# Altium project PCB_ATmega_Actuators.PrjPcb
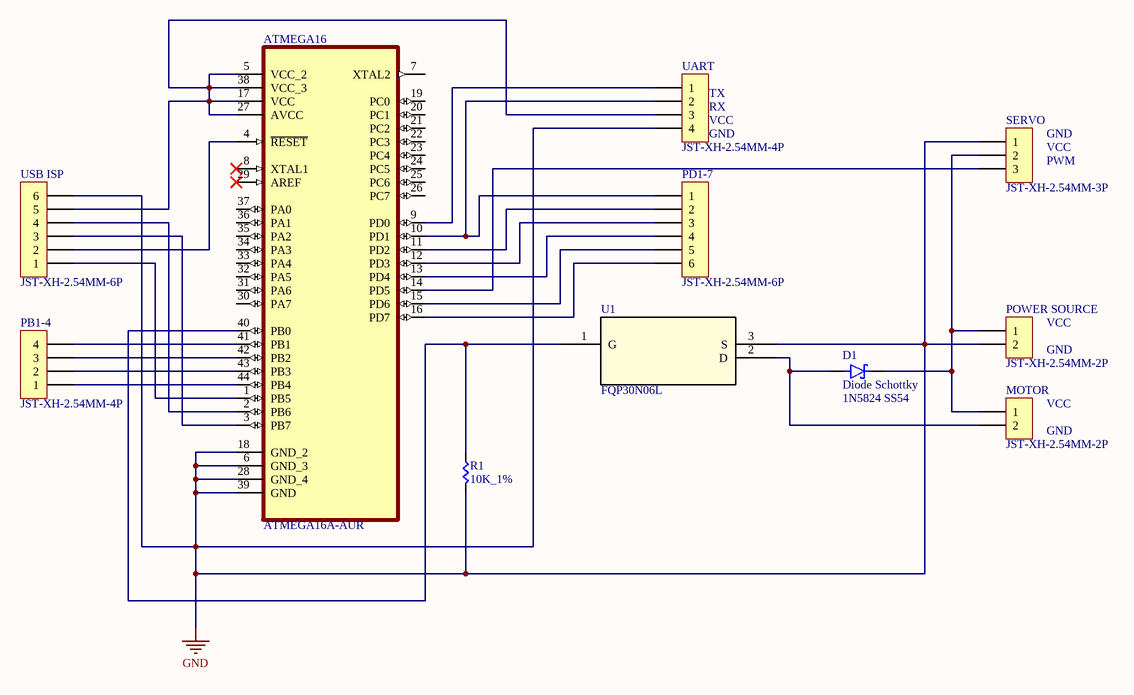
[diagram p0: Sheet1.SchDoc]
1 sheet, 11 parts. Net scope: global (net labels, ports and power ports of the same name join across sheets).
Board file: PCB1.PcbDoc

## Sheet Sheet1.SchDoc
size A3; SheetNumber: 1; SheetTotal: 1

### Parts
ATMEGA16  ATMEGA16A-AUR  [ATmega16_SMD]
D1  Diode Schottky  [1N5824 SS54]
MOTOR  Name: JST-XH-2.54MM-2P  [JST XH 2P-H 2.54mm]  (hidden comment: CN_JST_XH_2P_2.54MM)
PB1-4  Name: JST-XH-2.54MM-4P  [JST XH 4P-H 2.54mm]  (hidden comment: CN_JST_XH_4P_2.54MM)
PD1-7  Name: JST-XH-2.54MM-6P  [JST XH 6P-H 2.54mm]  (hidden comment: CN_JST_XH_6P_2.54MM)
POWER_SOURCE  Name: JST-XH-2.54MM-2P  [JST XH 2P-H 2.54mm]  (hidden comment: CN_JST_XH_2P_2.54MM)
R1  10K_1%  [RES 0805_2012]
SERVO  Name: JST-XH-2.54MM-3P  [JST XH 3P-H 2.54mm]  (hidden comment: CN_JST_XH_3P_2.54MM)
U1  FQP30N06L  [TO-220]
UART  Name: JST-XH-2.54MM-4P  [JST XH 4P-H 2.54mm]  (hidden comment: CN_JST_XH_4P_2.54MM)
USB_ISP  Name: JST-XH-2.54MM-6P  [JST XH 6P-H 2.54mm]  (hidden comment: CN_JST_XH_6P_2.54MM)

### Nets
GND: ATMEGA16.6(GND_3) ATMEGA16.18(GND_2) ATMEGA16.28(GND_4) ATMEGA16.39(GND) POWER_SOURCE.2 R1.2 SERVO.1 U1.3(S) UART.4 USB_ISP.6
NetATMEGA16_1: ATMEGA16.1(PB5) USB_ISP.1
NetATMEGA16_2: ATMEGA16.2(PB6) USB_ISP.4
NetATMEGA16_3: ATMEGA16.3(PB7) USB_ISP.3
NetATMEGA16_4: ATMEGA16.4(~{RESET}) USB_ISP.2
NetATMEGA16_5: ATMEGA16.5(VCC_2) ATMEGA16.17(VCC) ATMEGA16.27(AVCC) ATMEGA16.38(VCC_3) UART.3 USB_ISP.5
NetATMEGA16_9: ATMEGA16.9(PD0) UART.1
NetATMEGA16_10: ATMEGA16.10(PD1) PD1-7.1 UART.2
NetATMEGA16_11: ATMEGA16.11(PD2) PD1-7.2
NetATMEGA16_12: ATMEGA16.12(PD3) PD1-7.3
NetATMEGA16_13: ATMEGA16.13(PD4) PD1-7.4
NetATMEGA16_14: ATMEGA16.14(PD5) SERVO.3
NetATMEGA16_15: ATMEGA16.15(PD6) PD1-7.5
NetATMEGA16_16: ATMEGA16.16(PD7) PD1-7.6
NetATMEGA16_40: ATMEGA16.40(PB0) R1.1 U1.1(G)
NetATMEGA16_41: ATMEGA16.41(PB1) PB1-4.4
NetATMEGA16_42: ATMEGA16.42(PB2) PB1-4.3
NetATMEGA16_43: ATMEGA16.43(PB3) PB1-4.2
NetATMEGA16_44: ATMEGA16.44(PB4) PB1-4.1
NetD1_A: D1.A MOTOR.2 U1.2(D)
NetD1_C: D1.C MOTOR.1 POWER_SOURCE.1 SERVO.2

Not connected (* = marked no-connect by the designer): ATMEGA16 7(XTAL2) 8(XTAL1)* 19(PC0) 20(PC1) 21(PC2) 22(PC3) 23(PC4) 24(PC5) 25(PC6) 26(PC7) 29(AREF)* 30(PA7) 31(PA6) 32(PA5) 33(PA4) 34(PA3) 35(PA2) 36(PA1) 37(PA0)

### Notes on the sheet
- (near UART) TX
- (near UART) RX
- (near UART) VCC
- (near UART) GND
- (near SERVO) GND
- (near SERVO) VCC
- (near SERVO) PWM
- (near POWER_SOURCE) VCC
- (near MOTOR) VCC
- (near POWER_SOURCE) GND
- (near MOTOR) GND

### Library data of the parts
ATMEGA16 = ATMEGA16A-AUR: AVR AVRÂ® ATmega Microcontroller IC 8-Bit 16MHz 16KB (8K x 16) FLASH 44-TQFP (10x10); MF: Microchip
D1 = Diode Schottky 40 V 3A Surface Mount SMA
MOTOR POWER_SOURCE = CN_JST_XH_2P_2.54MM: JST_XH_2P_2.54MM; Current rating: 3A AC/DC; Voltage rating: 250V AC/DC
PB1-4 UART = CN_JST_XH_4P_2.54MM: JST_XH_4P_2.54MM; Current rating: 3A AC/DC; Voltage rating: 250V AC/DC
PD1-7 USB_ISP = CN_JST_XH_6P_2.54MM: JST_XH_6P_2.54MM; Current rating: 3A AC/DC; Voltage rating: 250V AC/DC
R1 = RES_1%_0805_10K: 125mW Thick Film Resistors 150V ±100ppm/℃ ±1% 10kΩ 0805 Chip Resistor - Surface Mount ROHS; Manufacturer: YAGEO; Mfr. Part: RC0805FR-0710KL
SERVO = CN_JST_XH_3P_2.54MM: JST_XH_3P_2.54MM; Current rating: 3A AC/DC; Voltage rating: 250V AC/DC
U1 = MOSFET-30N06L_1: No Description Available; Manufacturer_Name: onsemi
